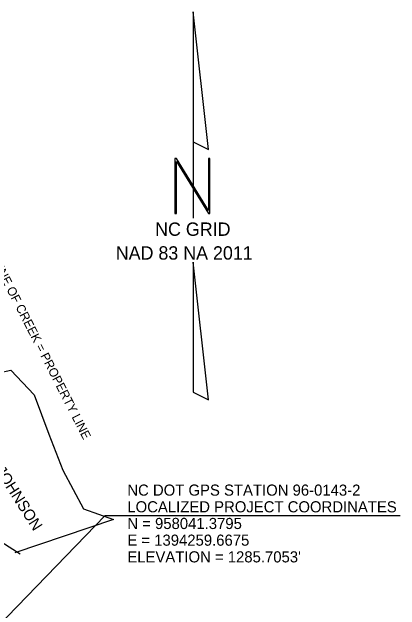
# Model space of a CAD drawing. Extents: x 1393723 to 1394549, y 957573 to 958412.
# Drawn here: x 1394315.1 to 1394489.5, y 958102.9 to 958371.7 of the extents above; entities that cross this region are included whole.
import ezdxf

# ---------------------------------------------------------------- set-up
doc = ezdxf.new("R2010")
doc.units = 0
for name, color, linetype in [('CTL GPS Vertical Text', 7, 'Continuous'), ('CTL North Arrow NAD 83 NA 2011 CELL', 7, 'Continuous'), ('Default', 7, 'Continuous'), ('Exist Property Line Text', 7, 'Continuous'), ('Exist Property Owner Text', 7, 'Continuous'), ('Exist Vegetation Woods Line', 7, 'Continuous')]:
    doc.layers.add(name, color=color, linetype=linetype)

msp = doc.modelspace()

# ---------------------------------------------------------------- linework, layer by layer
at = {"layer": 'CTL North Arrow NAD 83 NA 2011 CELL'}
msp.add_line((1394396.69, 958284.44), (1394396.69, 958284.44), dxfattribs=at)
for points in [[(1394396.54, 958371.73), (1394396.54, 958313.4), (1394403.41, 958309.97)], [(1394388.31, 958281.18), (1394389, 958281.18), (1394389, 958304.5), (1394403.41, 958281.18), (1394404.1, 958281.18), (1394404.1, 958305.87), (1394403.41, 958305.87), (1394403.41, 958282.54), (1394389, 958305.87), (1394388.31, 958305.87)], [(1394396.54, 958200.89), (1394403.41, 958197.48), (1394396.54, 958259.22)]]:
    msp.add_lwpolyline(points, close=True, dxfattribs=at)
msp.add_lwpolyline([(1394396.54, 958313.4), (1394396.54, 958279.1)], dxfattribs=at)
at = {"layer": 'Default'}
msp.add_line((1394356.95, 958145.42), (1394489.55, 958145.42), dxfattribs=at)
msp.add_lwpolyline([(1394260.2, 958045.54), (1394356.95, 958145.42)], dxfattribs=at)
at = {"layer": 'Exist Vegetation Woods Line'}
msp.add_lwpolyline([(1394318.85, 958128.04), (1394294.61, 958143.32), (1394270.07, 958149.61), (1394279.05, 958152.91), (1394281.74, 958166.99), (1394281.44, 958189.46), (1394280.24, 958201.75), (1394281.14, 958203.54), (1394314.66, 958210.74), (1394325.14, 958199.65), (1394331.73, 958181.97), (1394338.01, 958165.79), (1394347.29, 958148.41), (1394360.76, 958143.62), (1394316.46, 958128.63)], dxfattribs=at)

# ---------------------------------------------------------------- texts
at = {"layer": 'CTL GPS Vertical Text'}
for s, p in [('NC DOT GPS STATION 96-0143-2', (1394366.96, 958154.34)), ('LOCALIZED PROJECT COORDINATES', (1394366.96, 958146.84)), ('N = 958041.3795', (1394366.96, 958139.34)), ('E = 1394259.6675', (1394366.96, 958131.84)), ("ELEVATION = 1285.7053'", (1394366.96, 958124.34))]:
    msp.add_text(s, height=5, rotation=359.9944, dxfattribs=at).set_placement(p)
at = {"layer": 'CTL North Arrow NAD 83 NA 2011 CELL'}
for s, p in [('NC GRID', (1394379.46, 958271.11)), ('NAD 83 NA 2011', (1394361.77, 958260.42))]:
    msp.add_text(s, height=6, dxfattribs=at).set_placement(p)
at = {"layer": 'Exist Property Line Text'}
msp.add_text('CENTERLINE OF CREEK = PROPERTY LINE', height=4, rotation=297.0845, dxfattribs=at).set_placement((1394296.44, 958278.54))
at = {"layer": 'Exist Property Owner Text'}
msp.add_text('JAMES A. JOHNSON', height=5, rotation=302.4612, dxfattribs=at).set_placement((1394290.02, 958192.94))

doc.saveas('drawing.dxf')
